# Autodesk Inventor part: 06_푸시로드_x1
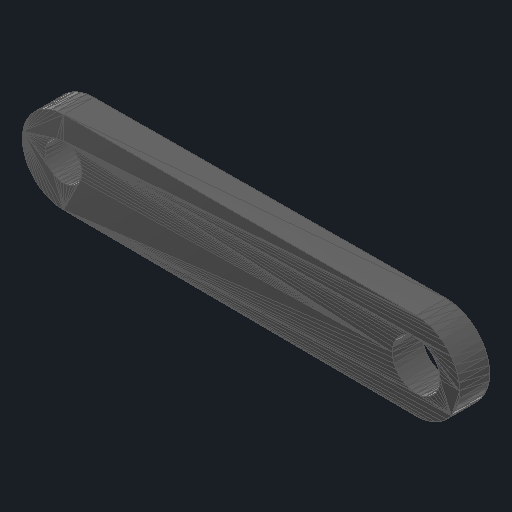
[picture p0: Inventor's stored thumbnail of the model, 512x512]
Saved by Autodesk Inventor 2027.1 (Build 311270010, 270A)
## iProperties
Created: 2026-11
Part Number: 06_푸시로드_x1
Material: 일반
Document SubType Name: Modeling
Designer: djshs
Density: 1 g/cm^3
Appearance: 기본값
Author: djshs
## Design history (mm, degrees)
node "06_푸시로드_x1"
  node "MeshFeature1"
